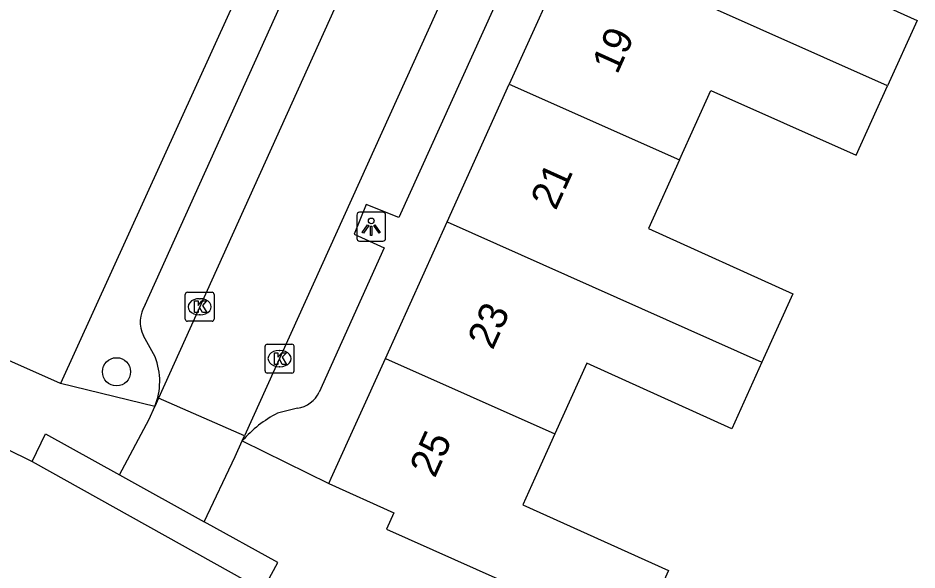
# Model space of a CAD drawing. Extents: x 161845 to 162341, y 381620 to 382158.
# Drawn here: x 162073.02 to 162104.17, y 381746.81 to 381765.94 of the extents above; entities that cross this region are included whole.
import ezdxf

# ---------------------------------------------------------------- set-up
doc = ezdxf.new("R2010")
doc.units = 0
for name, color, linetype in [('IMGEO_Boom', 7, 'Continuous'), ('IMGEO_Kolk', 7, 'Continuous'), ('IMGEO_Lichtpunt', 7, 'Continuous'), ('IMGEO_Pand', 7, 'Continuous'), ('IMGEO_Pand_nummerreeks', 7, 'Continuous'), ('IMGEO_Rijbaan_lokaal_open', 7, 'Continuous'), ('IMGEO_Voetpad_open', 7, 'Continuous')]:
    doc.layers.add(name, color=color, linetype=linetype)

msp = doc.modelspace()

# ---------------------------------------------------------------- linework, layer by layer
at = {"layer": 'IMGEO_Boom'}
msp.add_circle((162076.43, 381753.682), 0.489, dxfattribs=at)
at = {"layer": 'IMGEO_Kolk'}
for p, q in [((162078.813, 381755.511), (162078.813, 381756.363)), ((162078.888, 381756.437), (162079.74, 381756.437)), ((162079.814, 381756.363), (162079.814, 381755.511)), ((162079.301, 381756.217), (162079.326, 381756.217)), ((162079.324, 381755.657), (162079.299, 381755.657)), ((162079.74, 381755.437), (162078.888, 381755.437)), ((162081.58, 381753.714), (162081.58, 381754.566)), ((162081.655, 381754.64), (162082.507, 381754.64)), ((162082.068, 381754.42), (162082.093, 381754.42)), ((162082.581, 381754.566), (162082.581, 381753.714)), ((162082.091, 381753.86), (162082.066, 381753.86)), ((162082.507, 381753.64), (162081.655, 381753.64))]:
    msp.add_line(p, q, dxfattribs=at)
for points in [[(162078.813, 381755.511), (162078.813, 381756.363)], [(162078.888, 381756.437), (162079.74, 381756.437)], [(162079.814, 381756.363), (162079.814, 381755.511)], [(162079.134, 381756.137), (162079.257, 381756.137), (162079.257, 381755.986), (162079.387, 381756.137), (162079.551, 381756.137), (162079.405, 381755.986), (162079.558, 381755.737), (162079.406, 381755.737), (162079.321, 381755.901), (162079.257, 381755.834), (162079.257, 381755.737), (162079.134, 381755.737), (162079.134, 381756.137)], [(162079.74, 381755.437), (162078.888, 381755.437)], [(162081.58, 381753.714), (162081.58, 381754.566)], [(162081.655, 381754.64), (162082.507, 381754.64)], [(162082.581, 381754.566), (162082.581, 381753.714)], [(162081.901, 381754.34), (162082.024, 381754.34), (162082.024, 381754.189), (162082.154, 381754.34), (162082.318, 381754.34), (162082.172, 381754.189), (162082.325, 381753.94), (162082.173, 381753.94), (162082.088, 381754.104), (162082.024, 381754.037), (162082.024, 381753.94), (162081.901, 381753.94), (162081.901, 381754.34)], [(162082.507, 381753.64), (162081.655, 381753.64)]]:
    msp.add_lwpolyline(points, dxfattribs=at)
for centre, start, end in [((162078.89, 381756.361), 91.552, 178.448), ((162078.89, 381756.361), 91.552, 178.448), ((162079.738, 381756.361), 1.552, 88.448), ((162079.738, 381756.361), 1.552, 88.448), ((162078.89, 381755.513), 181.552, 268.448), ((162078.89, 381755.513), 181.552, 268.448), ((162079.738, 381755.513), 271.552, 358.448), ((162079.738, 381755.513), 271.552, 358.448), ((162081.657, 381754.564), 91.552, 178.448), ((162081.657, 381754.564), 91.552, 178.448), ((162082.505, 381754.564), 1.552, 88.448), ((162082.505, 381754.564), 1.552, 88.448), ((162081.657, 381753.716), 181.552, 268.448), ((162081.657, 381753.716), 181.552, 268.448), ((162082.505, 381753.716), 271.552, 358.448), ((162082.505, 381753.716), 271.552, 358.448)]:
    msp.add_arc(centre, 0.0765, start, end, dxfattribs=at)
for centre, major_axis, ratio, start_param, end_param in [((162079.3, 381755.937), (-0.387, 0.002), 0.722429, 4.712389, 7.853982), ((162079.325, 381755.937), (-0.39, 0.002), 0.717154, 1.570796, 4.712389), ((162082.067, 381754.14), (-0.387, 0.002), 0.722429, 4.712389, 7.853982), ((162082.092, 381754.14), (-0.39, 0.002), 0.717154, 1.570796, 4.712389)]:
    msp.add_ellipse(centre, major_axis=major_axis, ratio=ratio, start_param=start_param, end_param=end_param, dxfattribs=at)
at = {"layer": 'IMGEO_Lichtpunt'}
for p, q in [((162084.759, 381759.115), (162084.759, 381758.308)), ((162084.759, 381759.115), (162084.759, 381758.308)), ((162085.661, 381759.21), (162084.853, 381759.21)), ((162085.661, 381759.21), (162084.853, 381759.21)), ((162085.755, 381758.308), (162085.755, 381759.115)), ((162085.755, 381758.308), (162085.755, 381759.115)), ((162084.853, 381758.214), (162085.661, 381758.214)), ((162084.853, 381758.214), (162085.661, 381758.214))]:
    msp.add_line(p, q, dxfattribs=at)
for points in [[(162085.133, 381758.779), (162085.172, 381758.751), (162084.984, 381758.489), (162084.946, 381758.516), (162085.133, 381758.779)], [(162085.235, 381758.731), (162085.282, 381758.731), (162085.282, 381758.409), (162085.235, 381758.409), (162085.235, 381758.731)], [(162085.345, 381758.751), (162085.383, 381758.778), (162085.57, 381758.516), (162085.531, 381758.488), (162085.345, 381758.751)]]:
    msp.add_lwpolyline(points, dxfattribs=at)
msp.add_circle((162085.258, 381758.913), 0.0994, dxfattribs=at)
for centre, start, end in [((162084.853, 381759.115), 90, 180), ((162084.853, 381759.115), 90, 180), ((162085.661, 381759.115), 0, 90), ((162085.661, 381759.115), 0, 90), ((162084.853, 381758.308), 180, 270), ((162084.853, 381758.308), 180, 270), ((162085.661, 381758.308), 270, 0), ((162085.661, 381758.308), 270, 360)]:
    msp.add_arc(centre, 0.0946, start, end, dxfattribs=at)
at = {"layer": 'IMGEO_Pand'}
for points in [[(162100.229, 381770.46), (162099.172, 381768.121), (162104.172, 381765.858), (162103.149, 381763.595)], [(162092.219, 381768.471), (162090.043, 381763.653)], [(162103.149, 381763.595), (162092.219, 381768.471)], [(162087.886, 381758.88), (162090.043, 381763.653)], [(162090.043, 381763.653), (162095.939, 381761.023)], [(162095.939, 381761.023), (162097.027, 381763.433), (162102.061, 381761.187), (162103.149, 381763.595)], [(162095.939, 381761.023), (162094.867, 381758.649), (162099.869, 381756.389), (162098.796, 381754.013)], [(162085.748, 381754.149), (162087.886, 381758.88)], [(162087.886, 381758.88), (162098.796, 381754.013)], [(162083.788, 381749.81), (162083.874, 381750), (162085.748, 381754.149)], [(162085.748, 381754.149), (162091.62, 381751.529)], [(162098.796, 381754.013), (162097.756, 381751.711), (162092.728, 381753.983), (162091.62, 381751.529)], [(162091.62, 381751.529), (162090.929, 381750), (162090.511, 381749.074), (162095.561, 381746.795), (162094.462, 381744.361)], [(162083.788, 381749.81), (162086.038, 381748.793), (162085.784, 381748.23), (162094.462, 381744.361)]]:
    msp.add_lwpolyline(points, dxfattribs=at)
at = {"layer": 'IMGEO_Rijbaan_lokaal_open'}
for points in [[(162094.929, 381782.528), (162080.868, 381751.463)], [(162091.2, 381782.254), (162077.885, 381752.773)], [(162047.793, 381762.29), (162069.847, 381752.372), (162071.089, 381751.71), (162071.642, 381751.481), (162073.51, 381750.574)], [(162077.885, 381752.773), (162077.753, 381752.48)], [(162080.868, 381751.463), (162077.885, 381752.773)], [(162076.538, 381750.111), (162077.557, 381752.046), (162077.753, 381752.48)], [(162079.471, 381748.488), (162080.545, 381750.749), (162080.79, 381751.291)], [(162080.79, 381751.291), (162080.868, 381751.463)], [(162073.51, 381750.574), (162081.506, 381746.115)], [(162076.538, 381750.111), (162079.471, 381748.488)]]:
    msp.add_lwpolyline(points, dxfattribs=at)
at = {"layer": 'IMGEO_Voetpad_open'}
for points in [[(162089.747, 381786.804), (162074.49, 381753.282)], [(162077.427, 381756), (162088.368, 381780.23)], [(162095.341, 381779.181), (162086.211, 381759.034), (162085.08, 381759.486), (162084.665, 381758.456), (162085.708, 381757.978), (162083.457, 381752.979)], [(162074.49, 381753.282), (162068.219, 381756.057), (162068.579, 381756.936), (162067.446, 381757.401)], [(162077.765, 381754.199), (162077.369, 381754.933)], [(162077.753, 381752.48), (162074.49, 381753.282)], [(162082.698, 381752.417), (162082.013, 381752.249)], [(162073.51, 381750.574), (162073.964, 381751.536), (162076.538, 381750.111)], [(162080.79, 381751.291), (162083.788, 381749.81)], [(162081.506, 381746.115), (162082.026, 381747.073), (162079.471, 381748.488)]]:
    msp.add_lwpolyline(points, dxfattribs=at)
for centre, radius, start, end in [((162078.307, 381755.417), 1.056, 146.4825, 207.2947), ((162075.671, 381753.354), 2.258, 337.2236, 21.9765), ((162082.541, 381753.423), 1.018, 278.892, 334.144), ((162083.902, 381748.577), 4.129, 117.2298, 138.9148)]:
    msp.add_arc(centre, radius, start, end, dxfattribs=at)

# ---------------------------------------------------------------- texts
at = {"layer": 'IMGEO_Pand_nummerreeks'}
for s, rotation, p in [('19', 65.6839, (162093.781, 381763.96)), ('21', 65.6857, (162091.652, 381759.247)), ('23', 65.6857, (162089.466, 381754.412)), ('25', 65.6857, (162087.46, 381749.971))]:
    msp.add_text(s, height=1, rotation=rotation, dxfattribs=at).set_placement(p)

doc.saveas('drawing.dxf')
